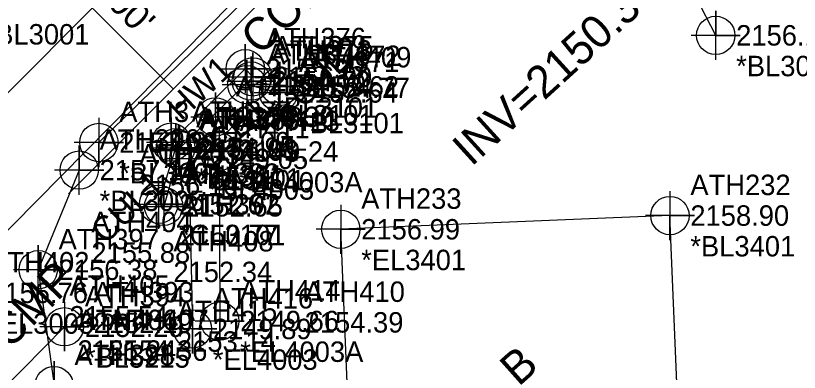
# Model space of a CAD drawing. Extents: x 890923 to 892150, y 696020 to 698102.
# Drawn here: x 891569.1 to 891664.9, y 696366.5 to 696410.1 of the extents above; entities that cross this region are included whole.
import ezdxf

# ---------------------------------------------------------------- set-up
doc = ezdxf.new("R2010")
doc.units = 0
for name, color, linetype in [('Exist Building', 7, 'Continuous'), ('Exist Building Cogo Elevation', 7, 'Continuous'), ('Exist Building Cogo Number', 7, 'Continuous'), ('Exist Building Cogo Point CELL', 7, 'Continuous'), ('Exist Building Text', 7, 'Continuous'), ('Exist DTM Breakline Cogo Elevation', 7, 'Continuous'), ('Exist DTM Breakline Cogo Number', 7, 'Continuous'), ('Exist DTM Drainline Cogo Comment', 7, 'Continuous'), ('Exist DTM Drainline Cogo Elevation', 7, 'Continuous'), ('Exist DTM Drainline Cogo Number', 7, 'Continuous'), ('Exist DTM Drainline Cogo Point CELL', 7, 'Continuous'), ('Exist Horizontal Alignment', 7, 'Continuous'), ('Exist Hydro Jurisdictional Stream or Body of Water', 7, 'Continuous'), ('Exist Right of Way Line', 7, 'Continuous'), ('Exist Right of Way Width CELL', 7, 'Continuous'), ('Exist Roads EOP', 7, 'Continuous'), ('Exist Roads EOP Cogo Comment', 7, 'Continuous'), ('Exist Roads EOP Cogo Elevation', 7, 'Continuous'), ('Exist Roads EOP Cogo Number', 7, 'Continuous'), ('Exist Roads EOP Cogo Point CELL', 7, 'Continuous'), ('Exist Roads Soil', 7, 'Continuous'), ('Exist Roads Soil Cogo Comment', 7, 'Continuous'), ('Exist Roads Soil Cogo Elevation', 7, 'Continuous'), ('Exist Roads Soil Cogo Number', 7, 'Continuous'), ('Exist Roads Soil Cogo Point CELL', 7, 'Continuous'), ('Exist Structure Major Bridge WW', 7, 'Continuous'), ('Exist Structure Major Deck Tunnel Box Culvert', 7, 'Continuous'), ('Exist Structure Major Deck Tunnel Box Culvert Cogo Comment', 7, 'Continuous'), ('Exist Structure Major Deck Tunnel Box Culvert Cogo Elevation', 7, 'Continuous'), ('Exist Structure Major Deck Tunnel Box Culvert Cogo Number', 7, 'Continuous'), ('Exist Structure Major Deck Tunnel Box Culvert Cogo Point CELL', 7, 'Continuous'), ('Exist Structure Major Deck Tunnel Box Culvert Text', 7, 'Continuous'), ('Exist Structure Minor Pipes CMP 15 Inch', 7, 'Continuous'), ('Exist Structure Minor Pipes CMP 15 Inch Cogo Comment', 7, 'Continuous'), ('Exist Structure Minor Pipes CMP 15 Inch Cogo Elevation', 7, 'Continuous'), ('Exist Structure Minor Pipes CMP 15 Inch Cogo Number', 7, 'Continuous'), ('Exist Structure Minor Pipes CMP 15 Inch Cogo Point CELL', 7, 'Continuous'), ('Exist Structure Minor Pipes CMP 15 Inch Text', 7, 'Continuous'), ('Exist Structure Minor Pipes CMP 18 Inch Invert', 7, 'Continuous'), ('Exist Utilities Telephone UG FO SUE LOS B', 7, 'Continuous')]:
    doc.layers.add(name, color=color, linetype=linetype)

msp = doc.modelspace()

# ---------------------------------------------------------------- linework, layer by layer
at = {"layer": 'Exist Building'}
for p, q in [((891649.073, 696385.664), (891608.819, 696383.987)), ((891652.318, 696307.783), (891649.073, 696385.664)), ((891612.065, 696306.083), (891608.819, 696383.987))]:
    msp.add_line(p, q, dxfattribs=at)
at = {"layer": 'Exist Building Cogo Point CELL'}
for points in [[(891649.073, 696388.664), (891649.073, 696382.664), (891649.073, 696385.664), (891652.073, 696385.664), (891646.073, 696385.664)], [(891608.819, 696386.987), (891608.819, 696380.987), (891608.819, 696383.987), (891611.819, 696383.987), (891605.819, 696383.987)]]:
    msp.add_lwpolyline(points, dxfattribs=at)
for centre in [(891649.073, 696385.664), (891608.819, 696383.987)]:
    msp.add_circle(centre, 2.344, dxfattribs=at)
at = {"layer": 'Exist DTM Drainline Cogo Point CELL'}
for points in [[(891590.243, 696395.606), (891590.243, 696389.606), (891590.243, 696392.606), (891593.243, 696392.606), (891587.243, 696392.606)], [(891593.931, 696396.487), (891593.931, 696390.487), (891593.931, 696393.487), (891596.931, 696393.487), (891590.931, 696393.487)], [(891594.017, 696375.769), (891594.017, 696369.769), (891594.017, 696372.769), (891597.017, 696372.769), (891591.017, 696372.769)], [(891590.668, 696374.8), (891590.668, 696368.8), (891590.668, 696371.8), (891593.668, 696371.8), (891587.668, 696371.8)]]:
    msp.add_lwpolyline(points, dxfattribs=at)
for centre in [(891593.931, 696393.487), (891590.243, 696392.606), (891594.017, 696372.769), (891590.668, 696371.8)]:
    msp.add_circle(centre, 2.344, dxfattribs=at)
at = {"layer": 'Exist Horizontal Alignment'}
msp.add_line((891565.623, 696398.226), (891680.932, 696513.665), dxfattribs=at)
at = {"layer": 'Exist Hydro Jurisdictional Stream or Body of Water'}
for p, q in [((891593.931, 696393.487), (891594.017, 696372.769)), ((891590.243, 696392.606), (891590.668, 696371.8))]:
    msp.add_line(p, q, dxfattribs=at)
at = {"layer": 'Exist Right of Way Line'}
msp.add_line((891575.528, 696388.332), (891690.837, 696503.771), dxfattribs=at)
at = {"layer": 'Exist Right of Way Width CELL'}
for p in [(891568.522, 696420.938), (891588.332, 696401.15)]:
    msp.add_line(p, (891579.855, 696409.618), dxfattribs=at)
at = {"layer": 'Exist Roads EOP'}
msp.add_lwpolyline([(891579.226, 696394.597), (891612.032, 696426.614), (891614.471, 696428.879), (891616.923, 696429.851), (891641.094, 696453.353), (891669.722, 696482.231), (891676.576, 696492.219), (891688.577, 696506.235)], dxfattribs=at)
at = {"layer": 'Exist Roads EOP Cogo Point CELL'}
msp.add_lwpolyline([(891579.226, 696397.597), (891579.226, 696391.597), (891579.226, 696394.597), (891582.226, 696394.597), (891576.226, 696394.597)], dxfattribs=at)
msp.add_circle((891579.226, 696394.597), 2.344, dxfattribs=at)
at = {"layer": 'Exist Roads Soil'}
for points in [[(891654.678, 696407.7), (891645.077, 696426.287), (891632.002, 696433.016), (891613.77, 696428.228)], [(891576.823, 696391.217), (891571.807, 696379.036), (891573.744, 696364.875), (891577.147, 696353.266)]]:
    msp.add_lwpolyline(points, dxfattribs=at)
at = {"layer": 'Exist Roads Soil Cogo Point CELL'}
for points in [[(891654.678, 696404.7), (891654.678, 696410.7), (891654.678, 696407.7), (891657.678, 696407.7), (891651.678, 696407.7)], [(891576.823, 696388.217), (891576.823, 696394.217), (891576.823, 696391.217), (891579.823, 696391.217), (891573.823, 696391.217)], [(891571.807, 696376.036), (891571.807, 696382.036), (891571.807, 696379.036), (891574.807, 696379.036), (891568.807, 696379.036)], [(891573.744, 696361.875), (891573.744, 696367.875), (891573.744, 696364.875), (891576.744, 696364.875), (891570.744, 696364.875)]]:
    msp.add_lwpolyline(points, dxfattribs=at)
for centre in [(891654.678, 696407.7), (891576.823, 696391.217), (891571.807, 696379.036), (891573.744, 696364.875)]:
    msp.add_circle(centre, 2.344, dxfattribs=at)
at = {"layer": 'Exist Structure Major Bridge WW'}
msp.add_line((891586.538, 696387.04), (891587.156, 696386.792), dxfattribs=at)
at = {"layer": 'Exist Structure Major Deck Tunnel Box Culvert'}
for points in [[(891598.063, 696402.622), (891597.135, 696403.617), (891588.075, 696394.641), (891588.979, 696393.747), (891598.063, 696402.622)], [(891601.208, 696400.72), (891601.371, 696401.454), (891597.862, 696402.104), (891597.323, 696401.674), (891601.208, 696400.72)], [(891588.626, 696393.957), (891589.112, 696393.616), (891587.156, 696386.792), (891586.538, 696387.04), (891588.626, 696393.957)]]:
    msp.add_lwpolyline(points, dxfattribs=at)
at = {"layer": 'Exist Structure Major Deck Tunnel Box Culvert Cogo Point CELL'}
for points in [[(891594.135, 696403.617), (891600.135, 696403.617), (891597.135, 696403.617), (891597.135, 696406.617), (891597.135, 696400.617)], [(891595.063, 696402.622), (891601.063, 696402.622), (891598.063, 696402.622), (891598.063, 696405.622), (891598.063, 696399.622)], [(891594.323, 696401.674), (891600.323, 696401.674), (891597.323, 696401.674), (891597.323, 696404.674), (891597.323, 696398.674)], [(891594.862, 696402.104), (891600.862, 696402.104), (891597.862, 696402.104), (891597.862, 696405.104), (891597.862, 696399.104)], [(891598.371, 696401.454), (891604.371, 696401.454), (891601.371, 696401.454), (891601.371, 696404.454), (891601.371, 696398.454)], [(891598.208, 696400.72), (891604.208, 696400.72), (891601.208, 696400.72), (891601.208, 696403.72), (891601.208, 696397.72)], [(891590.488, 696397.729), (891596.488, 696397.729), (891593.488, 696397.729), (891593.488, 696400.729), (891593.488, 696394.729)], [(891585.075, 696394.641), (891591.075, 696394.641), (891588.075, 696394.641), (891588.075, 696397.641), (891588.075, 696391.641)], [(891585.626, 696393.957), (891591.626, 696393.957), (891588.626, 696393.957), (891588.626, 696396.957), (891588.626, 696390.957)], [(891585.979, 696393.747), (891591.979, 696393.747), (891588.979, 696393.747), (891588.979, 696396.747), (891588.979, 696390.747)], [(891586.112, 696393.616), (891592.112, 696393.616), (891589.112, 696393.616), (891589.112, 696396.616), (891589.112, 696390.616)], [(891583.538, 696387.04), (891589.538, 696387.04), (891586.538, 696387.04), (891586.538, 696390.04), (891586.538, 696384.04)], [(891584.156, 696386.792), (891590.156, 696386.792), (891587.156, 696386.792), (891587.156, 696389.792), (891587.156, 696383.792)]]:
    msp.add_lwpolyline(points, dxfattribs=at)
for centre in [(891597.135, 696403.617), (891597.862, 696402.104), (891598.063, 696402.622), (891597.323, 696401.674), (891601.371, 696401.454), (891601.208, 696400.72), (891593.488, 696397.729), (891588.075, 696394.641), (891588.626, 696393.957), (891588.979, 696393.747), (891589.112, 696393.616), (891586.538, 696387.04), (891587.156, 696386.792)]:
    msp.add_circle(centre, 2.344, dxfattribs=at)
at = {"layer": 'Exist Structure Minor Pipes CMP 15 Inch'}
msp.add_line((891575.019, 696372.063), (891563.515, 696360.414), dxfattribs=at)
at = {"layer": 'Exist Structure Minor Pipes CMP 15 Inch Cogo Point CELL'}
msp.add_lwpolyline([(891575.019, 696375.063), (891575.019, 696369.063), (891575.019, 696372.063), (891578.019, 696372.063), (891572.019, 696372.063)], dxfattribs=at)
msp.add_circle((891575.019, 696372.063), 2.344, dxfattribs=at)
at = {"layer": 'Exist Utilities Telephone UG FO SUE LOS B'}
msp.add_lwpolyline([(891562.68, 696378.426), (891613.353, 696429.765), (891654.705, 696469.733), (891679.012, 696494.734), (891710.512, 696528.429), (891739.95, 696560.328)], dxfattribs=at)

# ---------------------------------------------------------------- texts
at = {"layer": 'Exist Building Cogo Elevation'}
for s, p in [('2158.90', (891651.573, 696384.414)), ('2156.99', (891611.319, 696382.737)), ('*BL3401', (891651.573, 696380.664)), ('*EL3401', (891611.319, 696378.987))]:
    msp.add_text(s, height=2.5, dxfattribs=at).set_placement(p)
at = {"layer": 'Exist Building Cogo Number'}
for s, p in [('ATH232', (891651.573, 696388.164)), ('ATH233', (891611.319, 696386.487))]:
    msp.add_text(s, height=2.5, dxfattribs=at).set_placement(p)
at = {"layer": 'Exist Building Text'}
msp.add_text('B', height=4, rotation=41.6491, dxfattribs=at).set_placement((891630.56, 696364.668))
at = {"layer": 'Exist DTM Breakline Cogo Elevation'}
for s, p in [('2154.77', (891605.188, 696400.029)), ('2156.10', (891584.191, 696388.165)), ('2150.77', (891589.132, 696382.033)), ('2155.88', (891578.317, 696379.879)), ('2152.34', (891588.343, 696377.526)), ('2155.54', (891575.623, 696372.099)), ('2152.19', (891578.591, 696371.303)), ('2154.39', (891604.396, 696371.356)), ('2153.14', (891588.781, 696369.011)), ('2155.24', (891576.616, 696367.91)), ('2154.36', (891580.417, 696367.902))]:
    msp.add_text(s, height=2.5, dxfattribs=at).set_placement(p)
at = {"layer": 'Exist DTM Breakline Cogo Number'}
for s, p in [('ATH409', (891605.188, 696403.779)), ('ATH403', (891584.191, 696391.915)), ('ATH392', (891589.132, 696385.783)), ('ATH404', (891578.317, 696383.629)), ('ATH408', (891588.343, 696381.276)), ('ATH405', (891575.623, 696375.849)), ('ATH393', (891578.591, 696375.053)), ('ATH410', (891604.396, 696375.106)), ('ATH415', (891588.781, 696372.761)), ('ATH406', (891576.616, 696371.66)), ('ATH407', (891580.417, 696371.652))]:
    msp.add_text(s, height=2.5, dxfattribs=at).set_placement(p)
at = {"layer": 'Exist DTM Drainline Cogo Comment'}
for s, p in [('*BL4003A', (891596.431, 696388.487)), ('*BL4003', (891592.743, 696387.606)), ('*EL4003A', (891596.517, 696367.769)), ('*EL4003', (891593.168, 696366.8))]:
    msp.add_text(s, height=2.5, dxfattribs=at).set_placement(p)
at = {"layer": 'Exist DTM Drainline Cogo Elevation'}
for s, p in [('2149.24', (891596.431, 696392.237)), ('2149.05', (891592.743, 696391.356)), ('2149.66', (891596.517, 696371.519)), ('2149.89', (891593.168, 696370.55))]:
    msp.add_text(s, height=2.5, dxfattribs=at).set_placement(p)
at = {"layer": 'Exist DTM Drainline Cogo Number'}
for s, p in [('ATH413', (891596.431, 696395.987)), ('ATH411', (891592.743, 696395.106)), ('ATH414', (891596.517, 696375.269)), ('ATH416', (891593.168, 696374.3))]:
    msp.add_text(s, height=2.5, dxfattribs=at).set_placement(p)
at = {"layer": 'Exist Right of Way Width CELL'}
msp.add_text("28.00'", height=3.2, rotation=315.03228, dxfattribs=at).set_placement((891575.959, 696415.665))
at = {"layer": 'Exist Roads EOP Cogo Comment'}
for s, p in [('*BL3001', (891565.252, 696406.577)), ('*BL3001A', (891581.726, 696389.597))]:
    msp.add_text(s, height=2.5, dxfattribs=at).set_placement(p)
at = {"layer": 'Exist Roads EOP Cogo Elevation'}
msp.add_text('2157.39', height=2.5, dxfattribs=at).set_placement((891581.726, 696393.347))
at = {"layer": 'Exist Roads EOP Cogo Number'}
msp.add_text('ATH3', height=2.5, dxfattribs=at).set_placement((891581.726, 696397.097))
at = {"layer": 'Exist Roads Soil Cogo Comment'}
for s, p in [('*BL3005', (891657.178, 696402.7)), ('*BL3005', (891579.323, 696386.217)), ('*EL3005', (891565.814, 696371.211))]:
    msp.add_text(s, height=2.5, dxfattribs=at).set_placement(p)
at = {"layer": 'Exist Roads Soil Cogo Elevation'}
for s, p in [('2156.14', (891657.178, 696406.45)), ('2157.14', (891579.323, 696389.967)), ('2156.38', (891574.307, 696377.786)), ('2156.76', (891565.814, 696374.961))]:
    msp.add_text(s, height=2.5, dxfattribs=at).set_placement(p)
at = {"layer": 'Exist Roads Soil Cogo Number'}
for s, p in [('ATH396', (891579.323, 696393.717)), ('ATH397', (891574.307, 696381.536)), ('ATH402', (891565.814, 696378.711)), ('ATH398', (891576.244, 696367.375))]:
    msp.add_text(s, height=2.5, dxfattribs=at).set_placement(p)
at = {"layer": 'Exist Structure Major Deck Tunnel Box Culvert Cogo Comment'}
for s, p in [('*BL3101', (891600.563, 696397.622)), ('*CL3101', (891599.823, 696396.674)), ('*BL3101', (891603.708, 696395.72)), ('*BL3101', (891591.126, 696388.957)), ('*CL3101', (891591.479, 696388.747)), ('*CL3101', (891589.038, 696382.04))]:
    msp.add_text(s, height=2.5, dxfattribs=at).set_placement(p)
at = {"layer": 'Exist Structure Major Deck Tunnel Box Culvert Cogo Elevation'}
for s, p in [('2155.95', (891599.635, 696402.367)), ('2154.72', (891600.362, 696400.854)), ('2156.00', (891600.563, 696401.372)), ('2154.90', (891599.823, 696400.424)), ('2152.62', (891603.871, 696400.204)), ('2152.64', (891603.708, 696399.47)), ('2154.30', (891595.988, 696396.479)), ('2156.09', (891590.575, 696393.391)), ('2154.95', (891591.126, 696392.707)), ('2156.08', (891591.479, 696392.497)), ('2154.91', (891591.612, 696392.366)), ('2152.67', (891589.038, 696385.79)), ('2152.65', (891589.656, 696385.542))]:
    msp.add_text(s, height=2.5, dxfattribs=at).set_placement(p)
at = {"layer": 'Exist Structure Major Deck Tunnel Box Culvert Cogo Number'}
for s, p in [('ATH376', (891599.635, 696406.117)), ('ATH373', (891600.362, 696404.604)), ('ATH375', (891600.563, 696405.122)), ('ATH374', (891599.823, 696404.174)), ('ATH372', (891603.871, 696403.954)), ('ATH371', (891603.708, 696403.22)), ('ATH383', (891595.988, 696400.229)), ('ATH377', (891590.575, 696397.141)), ('ATH379', (891591.126, 696396.457)), ('ATH378', (891591.479, 696396.247)), ('ATH380', (891591.612, 696396.116)), ('ATH382', (891589.038, 696389.54)), ('ATH381', (891589.656, 696389.292))]:
    msp.add_text(s, height=2.5, dxfattribs=at).set_placement(p)
at = {"layer": 'Exist Structure Major Deck Tunnel Box Culvert Text'}
for s, height, rotation, p in [('CONC HW', 4, 43.89235, (891598.972, 696405.11)), ('CUL2', 3, 44.07126, (891604.257, 696398.681)), ('HW1', 3, 43.07126, (891589.276, 696397.144)), ('CE1', 3, 41.07126, (891594.226, 696392.972)), ('CUL1', 3, 43.07126, (891579.994, 696382.054))]:
    msp.add_text(s, height=height, rotation=rotation, dxfattribs=at).set_placement(p)
at = {"layer": 'Exist Structure Minor Pipes CMP 15 Inch Cogo Comment'}
msp.add_text('*BL5215', height=2.5, dxfattribs=at).set_placement((891577.519, 696367.063))
at = {"layer": 'Exist Structure Minor Pipes CMP 15 Inch Cogo Elevation'}
msp.add_text('2152.29', height=2.5, dxfattribs=at).set_placement((891577.519, 696370.813))
at = {"layer": 'Exist Structure Minor Pipes CMP 15 Inch Cogo Number'}
msp.add_text('ATH394', height=2.5, dxfattribs=at).set_placement((891577.519, 696374.563))
at = {"layer": 'Exist Structure Minor Pipes CMP 15 Inch Text'}
msp.add_text('15" CMP', height=4, rotation=45.35882, dxfattribs=at).set_placement((891561.746, 696362.537))
at = {"layer": 'Exist Structure Minor Pipes CMP 18 Inch Invert'}
msp.add_text("INV=2150.39'", height=4, rotation=42.29152, dxfattribs=at).set_placement((891624.789, 696391.567))

doc.saveas('drawing.dxf')
